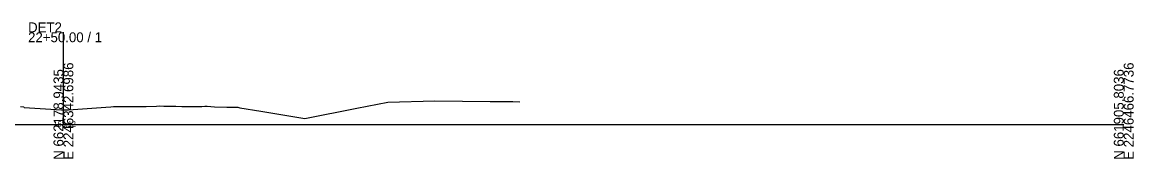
# Model space of a CAD drawing. Extents: x -26 to 603, y -10 to 9526.
# Drawn here: x 288.3 to 602.8, y 5490.3 to 5528.8 of the extents above; entities that cross this region are included whole.
import ezdxf

# ---------------------------------------------------------------- set-up
doc = ezdxf.new("R2010")
doc.units = 0
for name, color, linetype in [('Exist Cross Section Cell', 7, 'Continuous'), ('Exist XS Center Line Elevation Label', 7, 'Continuous'), ('Exist XS Ground Line', 7, 'Continuous')]:
    doc.layers.add(name, color=color, linetype=linetype)

msp = doc.modelspace()

# ---------------------------------------------------------------- linework, layer by layer
at = {"layer": 'Exist Cross Section Cell'}
for p, q in [((300, 5500), (300, 5526)), ((0, 5500), (300, 5500)), ((300, 5500), (600, 5500))]:
    msp.add_line(p, q, dxfattribs=at)
at = {"layer": 'Exist XS Ground Line'}
for p, q in [((287.86, 5505.02), (288.83, 5505)), ((288.83, 5505), (288.91, 5504.79)), ((288.91, 5504.79), (299.47, 5504.16)), ((299.47, 5504.16), (300, 5504.12)), ((300, 5504.12), (300.55, 5504.08)), ((300.55, 5504.08), (301.43, 5504.14)), ((301.43, 5504.14), (311.99, 5504.87)), ((311.99, 5504.87), (313.4, 5504.97)), ((313.4, 5504.97), (314.17, 5505.02)), ((314.17, 5505.02), (315.66, 5505.09)), ((315.66, 5505.09), (317.65, 5505.04)), ((317.65, 5505.04), (319.82, 5505.06)), ((319.82, 5505.06), (320.81, 5505.08)), ((320.81, 5505.08), (323.43, 5505.1)), ((323.43, 5505.1), (326.3, 5505.13)), ((326.3, 5505.13), (327.11, 5505.2)), ((327.11, 5505.2), (328.38, 5505.16)), ((328.38, 5505.16), (329.17, 5505.14)), ((329.17, 5505.14), (331.15, 5505.12)), ((331.15, 5505.12), (331.79, 5505.11)), ((331.79, 5505.11), (333.49, 5505.09)), ((333.49, 5505.09), (337.28, 5505.04)), ((337.28, 5505.04), (338.26, 5505.03)), ((338.26, 5505.03), (339.2, 5505.01)), ((339.2, 5505.01), (339.99, 5505.11)), ((339.99, 5505.11), (340.64, 5505.19)), ((340.64, 5505.19), (342.77, 5504.95)), ((342.77, 5504.95), (346.26, 5504.9)), ((346.26, 5504.9), (348.26, 5504.88)), ((348.26, 5504.88), (349.31, 5504.85)), ((349.31, 5504.85), (349.92, 5504.69)), ((349.92, 5504.69), (355.83, 5503.7)), ((355.83, 5503.7), (368.33, 5501.63)), ((368.33, 5501.63), (382.97, 5504.63)), ((382.97, 5504.63), (391.79, 5506.31)), ((391.79, 5506.31), (405.11, 5506.69)), ((405.11, 5506.69), (420.7, 5506.42)), ((420.7, 5506.42), (427.13, 5506.51)), ((427.13, 5506.51), (429.18, 5506.41))]:
    msp.add_line(p, q, dxfattribs=at)

# ---------------------------------------------------------------- texts
at = {"layer": 'Exist Cross Section Cell'}
for s, p in [('22+50.00 / 1', (290, 5523.2)), ('DET2', (290, 5526))]:
    msp.add_text(s, height=2.8, dxfattribs=at).set_placement(p)
for s, p in [('E 2246342.6986', (302.8, 5490)), ('E 2246466.7736', (602.8, 5490)), ('N 662178.9435', (300, 5490)), ('N 661905.8036', (600, 5490))]:
    msp.add_text(s, height=2.8, rotation=90, dxfattribs=at).set_placement(p)
at = {"layer": 'Exist XS Center Line Elevation Label'}
msp.add_text('153.12', height=1.5, dxfattribs=at).set_placement((297.2, 5499.37))

doc.saveas('drawing.dxf')
